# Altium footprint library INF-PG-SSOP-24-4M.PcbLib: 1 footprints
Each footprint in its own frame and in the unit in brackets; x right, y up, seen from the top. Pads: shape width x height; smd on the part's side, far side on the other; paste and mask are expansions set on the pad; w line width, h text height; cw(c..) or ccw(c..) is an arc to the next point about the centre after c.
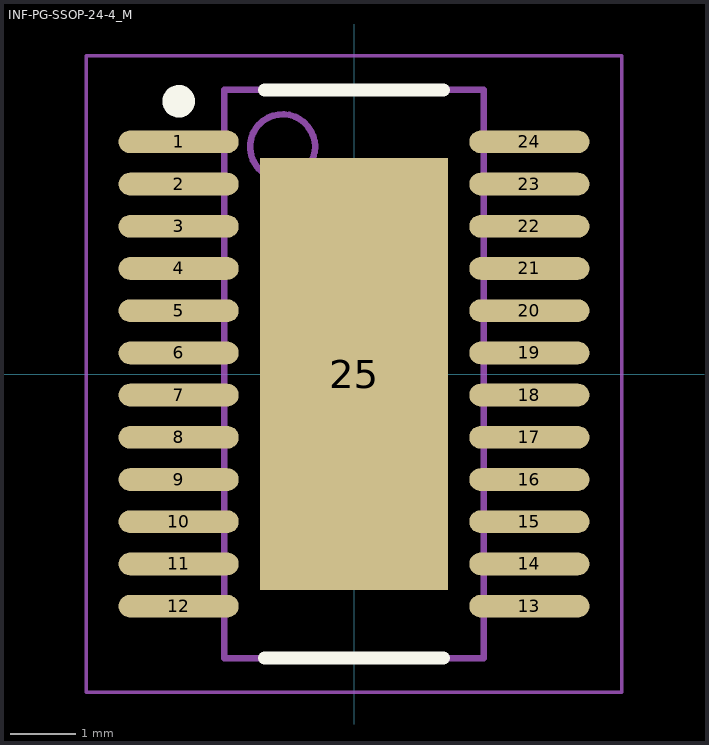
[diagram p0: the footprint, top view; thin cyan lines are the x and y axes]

## INF-PG-SSOP-24-4_M [mm] "SOP, 24-Leads, Body 8.65x3.9mm, Pitch 0.65mm, Thermal Pad 6.65x2.9mm, IPC Low Density"
height 1.7
pads (25):
  oval 1.85x0.35 smd: 1(-2.7,3.575) 2(-2.7,2.925) 3(-2.7,2.275) 4(-2.7,1.625) 5(-2.7,0.975) 6(-2.7,0.325) 7(-2.7,-0.325) 8(-2.7,-0.975) 9(-2.7,-1.625) 10(-2.7,-2.275) 11(-2.7,-2.925) 12(-2.7,-3.575) 13(2.7,-3.575) 14(2.7,-2.925) 15(2.7,-2.275) 16(2.7,-1.625) 17(2.7,-0.975) 18(2.7,-0.325) 19(2.7,0.325) 20(2.7,0.975) 21(2.7,1.625) 22(2.7,2.275) 23(2.7,2.925) 24(2.7,3.575)
  rect 2.9x6.65 smd: 25(0,0)
Top Overlay:
  circle w0.25: c-2.7,4.2 r0.125
  lines w0.2: -1.375,-4.375 1.375,-4.375 ; -1.375,4.375 1.375,4.375
Mechanical 13:
  circle w0.1: c-1.1,3.5 r0.5
  lines w0.1: -2,-4.375 2,-4.375 2,4.375 -2,4.375 -2,-4.375
Mechanical 15:
  lines w0.05: -4.125,-4.9 4.125,-4.9 4.125,4.9 -4.125,4.9 -4.125,-4.9
  lines w0.1: -0.5,0 0.5,0 ; 0,-0.5 0,0.5
3D body: height 1.7, standoff 0, extent -2,-4.375 2,4.375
